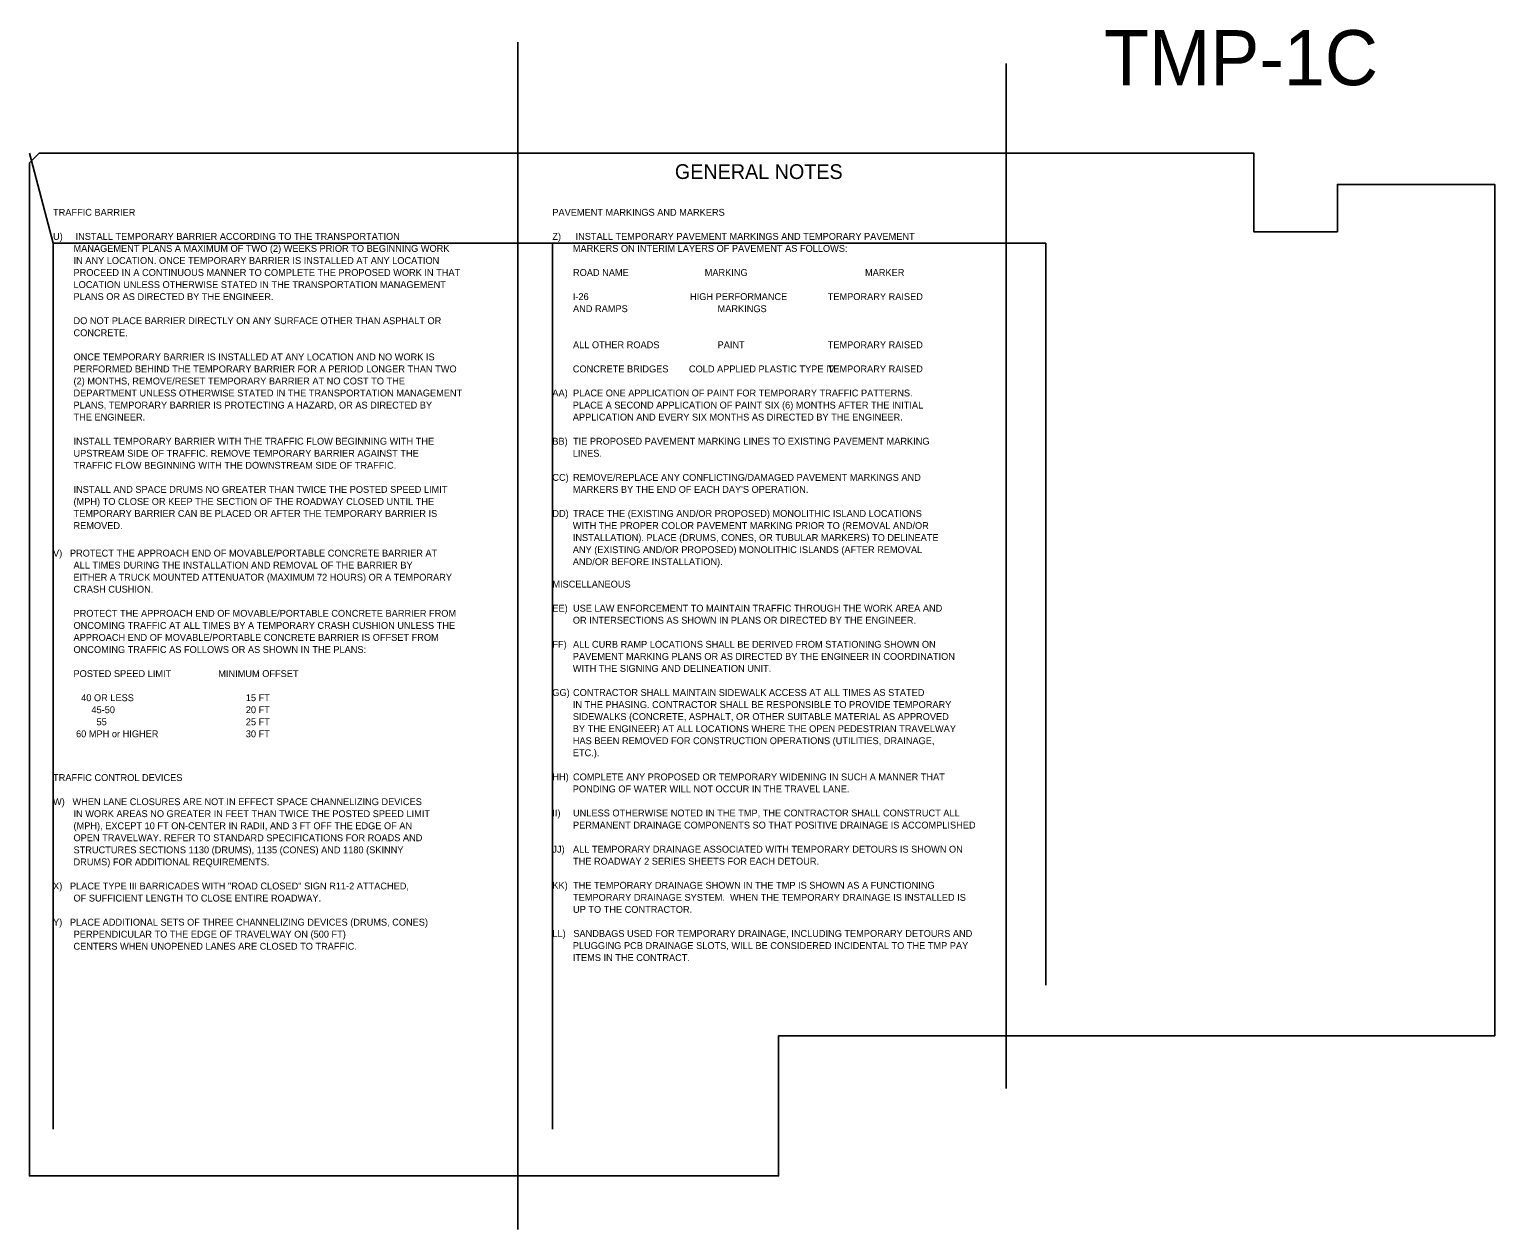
# Model space of a CAD drawing. Extents: x 2485109 to 2490507, y 368607 to 371384.
# Drawn here: x 2489017 to 2490507, y 370164 to 371384 of the extents above; entities that cross this region are included whole.
import ezdxf

# ---------------------------------------------------------------- set-up
doc = ezdxf.new("R2010")
doc.units = 0
for name, color, linetype in [('Scratch_Level_2', 7, 'Continuous'), ('Scratch_Level_3', 7, 'Continuous'), ('Scratch_Level_4', 7, 'Continuous'), ('TC SHEET LAYOUT SHAPE', 7, 'Continuous'), ('TC SHEET TEXT', 7, 'Continuous')]:
    doc.layers.add(name, color=color, linetype=linetype)

msp = doc.modelspace()

# ---------------------------------------------------------------- linework, layer by layer
at = {"layer": 'Scratch_Level_2'}
for p, q in [((2489513.2, 370163.7), (2489513.2, 371371.1)), ((2490009.9, 370307.3), (2490009.9, 371349.4))]:
    msp.add_line(p, q, dxfattribs=at)
at = {"layer": 'Scratch_Level_3'}
msp.add_line((2489016.6, 371258.3), (2489016.6, 371258.3), dxfattribs=at)
at = {"layer": 'Scratch_Level_4'}
for p, q in [((2489016.6, 371258.3), (2489040.7, 371166.6)), ((2489040.7, 371166.6), (2489040.7, 370266)), ((2489040.7, 371166.6), (2490050.1, 371166.6)), ((2489548.4, 371166.6), (2489548.4, 370266)), ((2490050.1, 371166.6), (2490050.1, 370412.4))]:
    msp.add_line(p, q, dxfattribs=at)
at = {"layer": 'TC SHEET LAYOUT SHAPE'}
msp.add_lwpolyline([(2489016.6, 370666.8), (2489016.6, 370976.2), (2489016.6, 371248.3), (2489026.6, 371258.3), (2489469.6, 371258.3), (2489940.6, 371258.3), (2490261.6, 371258.3), (2490261.6, 371178.3), (2490346.6, 371178.3), (2490346.6, 371226.3), (2490506.6, 371226.3), (2490506.6, 370891.3), (2490506.6, 370612.1), (2490506.6, 370360.8), (2489778.4, 370360.8), (2489778.4, 370218.3), (2489608.9, 370218.3), (2489256.1, 370218.3), (2489016.6, 370218.3)], close=True, dxfattribs=at)

# ---------------------------------------------------------------- texts
msp.add_text('TMP-1C', height=56, rotation=0.0001, dxfattribs=at).set_placement((2490109.2, 371327.2))
at = {"layer": 'TC SHEET TEXT'}
msp.add_text('GENERAL NOTES', height=15, rotation=359.994, dxfattribs=at).set_placement((2489673, 371231.9))
for s, p in [('TRAFFIC BARRIER', (2489040.7, 371194.5)), ('PAVEMENT MARKINGS AND MARKERS', (2489548.4, 371194.5)), ('U)     INSTALL TEMPORARY BARRIER ACCORDING TO THE TRANSPORTATION', (2489040.7, 371170)), ('Z)', (2489548.4, 371170)), (' INSTALL TEMPORARY PAVEMENT MARKINGS AND TEMPORARY PAVEMENT', (2489569.4, 371170)), ('        MANAGEMENT PLANS A MAXIMUM OF TWO (2) WEEKS PRIOR TO BEGINNING WORK', (2489040.7, 371157.8)), ('        MARKERS ON INTERIM LAYERS OF PAVEMENT AS FOLLOWS:', (2489548.4, 371157.8)), ('        IN ANY LOCATION. ONCE TEMPORARY BARRIER IS INSTALLED AT ANY LOCATION', (2489040.7, 371145.5)), ('        PROCEED IN A CONTINUOUS MANNER TO COMPLETE THE PROPOSED WORK IN THAT', (2489040.7, 371133.3)), ('ROAD NAME', (2489569.4, 371133.3)), ('MARKING', (2489703.3, 371133.3)), ('MARKER', (2489866.3, 371133.3)), ('        LOCATION UNLESS OTHERWISE STATED IN THE TRANSPORTATION MANAGEMENT', (2489040.7, 371121)), ('        PLANS OR AS DIRECTED BY THE ENGINEER.', (2489040.7, 371108.8)), ('        I-26', (2489548.4, 371108.8)), ('HIGH PERFORMANCE', (2489688.4, 371108.8)), ('TEMPORARY RAISED', (2489828.4, 371108.8)), ('AND RAMPS', (2489569.4, 371096.5)), ('MARKINGS', (2489716.4, 371096.5)), ('        DO NOT PLACE BARRIER DIRECTLY ON ANY SURFACE OTHER THAN ASPHALT OR', (2489040.7, 371084.3)), ('        CONCRETE.', (2489040.7, 371072)), ('ALL OTHER ROADS                   ', (2489569.4, 371059.8)), ('PAINT             ', (2489716.4, 371059.8)), ('TEMPORARY RAISED', (2489828.4, 371059.8)), ('        ONCE TEMPORARY BARRIER IS INSTALLED AT ANY LOCATION AND NO WORK IS', (2489040.7, 371047.5)), ('        PERFORMED BEHIND THE TEMPORARY BARRIER FOR A PERIOD LONGER THAN TWO', (2489040.7, 371035.3)), ('        CONCRETE BRIDGES        COLD APPLIED PLASTIC TYPE IV', (2489548.4, 371035.3)), ('TEMPORARY RAISED', (2489828.4, 371035.3)), ('        (2) MONTHS, REMOVE/RESET TEMPORARY BARRIER AT NO COST TO THE', (2489040.7, 371023)), ('        DEPARTMENT UNLESS OTHERWISE STATED IN THE TRANSPORTATION MANAGEMENT', (2489040.7, 371010.8)), ('AA)', (2489548.4, 371010.8)), ('PLACE ONE APPLICATION OF PAINT FOR TEMPORARY TRAFFIC PATTERNS.', (2489569.4, 371010.8)), ('        PLANS, TEMPORARY BARRIER IS PROTECTING A HAZARD, OR AS DIRECTED BY', (2489040.7, 370998.5)), ('        PLACE A SECOND APPLICATION OF PAINT SIX (6) MONTHS AFTER THE INITIAL', (2489548.4, 370998.5)), ('        THE ENGINEER.', (2489040.7, 370986.3)), ('        APPLICATION AND EVERY SIX MONTHS AS DIRECTED BY THE ENGINEER.', (2489548.4, 370986.3)), ('        INSTALL TEMPORARY BARRIER WITH THE TRAFFIC FLOW BEGINNING WITH THE', (2489040.7, 370961.8)), ('BB)', (2489548.4, 370961.8)), ('TIE PROPOSED PAVEMENT MARKING LINES TO EXISTING PAVEMENT MARKING', (2489569.4, 370961.8)), ('        UPSTREAM SIDE OF TRAFFIC. REMOVE TEMPORARY BARRIER AGAINST THE', (2489040.7, 370949.5)), ('        LINES.', (2489548.4, 370949.5)), ('        TRAFFIC FLOW BEGINNING WITH THE DOWNSTREAM SIDE OF TRAFFIC. ', (2489040.7, 370937.3)), ('CC)', (2489548.4, 370925)), ('REMOVE/REPLACE ANY CONFLICTING/DAMAGED PAVEMENT MARKINGS AND', (2489569.4, 370925)), ('        (MPH) TO CLOSE OR KEEP THE SECTION OF THE ROADWAY CLOSED UNTIL THE', (2489040.7, 370900.5)), ('        INSTALL AND SPACE DRUMS NO GREATER THAN TWICE THE POSTED SPEED LIMIT', (2489040.7, 370912.8)), ("        MARKERS BY THE END OF EACH DAY'S OPERATION.", (2489548.4, 370912.8)), ('        TEMPORARY BARRIER CAN BE PLACED OR AFTER THE TEMPORARY BARRIER IS', (2489040.7, 370888.3)), ('DD)', (2489548.4, 370888.3)), ('TRACE THE (EXISTING AND/OR PROPOSED) MONOLITHIC ISLAND LOCATIONS', (2489569.4, 370888.3)), ('        REMOVED.', (2489040.7, 370876)), ('        WITH THE PROPER COLOR PAVEMENT MARKING PRIOR TO (REMOVAL AND/OR', (2489548.4, 370876)), ('        INSTALLATION). PLACE (DRUMS, CONES, OR TUBULAR MARKERS) TO DELINEATE', (2489548.4, 370863.8)), ('V)   PROTECT THE APPROACH END OF MOVABLE/PORTABLE CONCRETE BARRIER AT', (2489040.7, 370848)), ('        ANY (EXISTING AND/OR PROPOSED) MONOLITHIC ISLANDS (AFTER REMOVAL', (2489548.4, 370851.5)), ('        ALL TIMES DURING THE INSTALLATION AND REMOVAL OF THE BARRIER BY', (2489040.7, 370835.8)), ('        AND/OR BEFORE INSTALLATION).', (2489548.4, 370839.3)), ('        CRASH CUSHION. ', (2489040.7, 370811.3)), ('        EITHER A TRUCK MOUNTED ATTENUATOR (MAXIMUM 72 HOURS) OR A TEMPORARY', (2489040.7, 370823.5)), ('MISCELLANEOUS', (2489548.4, 370816.5)), ('        PROTECT THE APPROACH END OF MOVABLE/PORTABLE CONCRETE BARRIER FROM', (2489040.7, 370786.8)), ('EE)', (2489548.4, 370792)), ('USE LAW ENFORCEMENT TO MAINTAIN TRAFFIC THROUGH THE WORK AREA AND', (2489569.4, 370792)), ('        ONCOMING TRAFFIC AT ALL TIMES BY A TEMPORARY CRASH CUSHION UNLESS THE', (2489040.7, 370774.5)), ('        OR INTERSECTIONS AS SHOWN IN PLANS OR DIRECTED BY THE ENGINEER.', (2489548.4, 370779.8)), ('        APPROACH END OF MOVABLE/PORTABLE CONCRETE BARRIER IS OFFSET FROM', (2489040.7, 370762.3)), ('FF)', (2489548.4, 370755.3)), ('ALL CURB RAMP LOCATIONS SHALL BE DERIVED FROM STATIONING SHOWN ON', (2489569.4, 370755.3)), ('        ONCOMING TRAFFIC AS FOLLOWS OR AS SHOWN IN THE PLANS: ', (2489040.7, 370750)), ('        PAVEMENT MARKING PLANS OR AS DIRECTED BY THE ENGINEER IN COORDINATION', (2489548.4, 370743)), ('        POSTED SPEED LIMIT ', (2489040.7, 370725.5)), ('MINIMUM OFFSET', (2489208.7, 370725.5)), ('        WITH THE SIGNING AND DELINEATION UNIT.', (2489548.4, 370730.8)), ('GG)', (2489548.4, 370706.3)), ('CONTRACTOR SHALL MAINTAIN SIDEWALK ACCESS AT ALL TIMES AS STATED', (2489569.4, 370706.3)), ('           40 OR LESS      ', (2489040.7, 370701)), ('15 FT', (2489236.7, 370701)), ('        IN THE PHASING. CONTRACTOR SHALL BE RESPONSIBLE TO PROVIDE TEMPORARY', (2489548.4, 370694)), ('               45-50     ', (2489040.7, 370688.8)), ('                 55      ', (2489040.7, 370676.5)), ('20 FT', (2489236.7, 370688.8)), ('25 FT', (2489236.7, 370676.5)), ('        SIDEWALKS (CONCRETE, ASPHALT, OR OTHER SUITABLE MATERIAL AS APPROVED', (2489548.4, 370681.8)), ('         60 MPH or HIGHER      ', (2489040.7, 370664.3)), ('30 FT', (2489236.7, 370664.3)), ('        BY THE ENGINEER) AT ALL LOCATIONS WHERE THE OPEN PEDESTRIAN TRAVELWAY', (2489548.4, 370669.5)), ('        HAS BEEN REMOVED FOR CONSTRUCTION OPERATIONS (UTILITIES, DRAINAGE,', (2489548.4, 370657.3)), ('        ETC.).', (2489548.4, 370645)), ('TRAFFIC CONTROL DEVICES', (2489040.7, 370619.8)), ('HH)', (2489548.4, 370620.5)), ('COMPLETE ANY PROPOSED OR TEMPORARY WIDENING IN SUCH A MANNER THAT', (2489569.4, 370620.5)), ('        PONDING OF WATER WILL NOT OCCUR IN THE TRAVEL LANE.', (2489548.4, 370608.3)), ('W)   WHEN LANE CLOSURES ARE NOT IN EFFECT SPACE CHANNELIZING DEVICES', (2489040.7, 370595.3)), ('        IN WORK AREAS NO GREATER IN FEET THAN TWICE THE POSTED SPEED LIMIT', (2489040.7, 370583.1)), ('II)', (2489548.4, 370583.8)), ('UNLESS OTHERWISE NOTED IN THE TMP, THE CONTRACTOR SHALL CONSTRUCT ALL', (2489569.4, 370583.8)), ('        OPEN TRAVELWAY. REFER TO STANDARD SPECIFICATIONS FOR ROADS AND', (2489040.7, 370558.6)), ('        (MPH), EXCEPT 10 FT ON-CENTER IN RADII, AND 3 FT OFF THE EDGE OF AN', (2489040.7, 370570.8)), ('PERMANENT DRAINAGE COMPONENTS SO THAT POSITIVE DRAINAGE IS ACCOMPLISHED', (2489569.4, 370571.5)), ('        STRUCTURES SECTIONS 1130 (DRUMS), 1135 (CONES) AND 1180 (SKINNY', (2489040.7, 370546.3)), ('JJ)', (2489548.4, 370547)), ('ALL TEMPORARY DRAINAGE ASSOCIATED WITH TEMPORARY DETOURS IS SHOWN ON', (2489569.4, 370547)), ('        DRUMS) FOR ADDITIONAL REQUIREMENTS.', (2489040.7, 370534.1)), ('THE ROADWAY 2 SERIES SHEETS FOR EACH DETOUR.', (2489569.4, 370534.8)), ('X)   PLACE TYPE III BARRICADES WITH "ROAD CLOSED" SIGN R11-2 ATTACHED,', (2489040.7, 370509.6)), ('        OF SUFFICIENT LENGTH TO CLOSE ENTIRE ROADWAY.', (2489040.7, 370497.3)), ('KK)', (2489548.4, 370510.3)), ('THE TEMPORARY DRAINAGE SHOWN IN THE TMP IS SHOWN AS A FUNCTIONING', (2489569.4, 370510.3)), ('TEMPORARY DRAINAGE SYSTEM.  WHEN THE TEMPORARY DRAINAGE IS INSTALLED IS', (2489569.4, 370498)), ('UP TO THE CONTRACTOR.', (2489569.4, 370485.8)), ('Y)   PLACE ADDITIONAL SETS OF THREE CHANNELIZING DEVICES (DRUMS, CONES)', (2489040.7, 370472.8)), ('PERPENDICULAR TO THE EDGE OF TRAVELWAY ON (500 FT)', (2489061.7, 370460.6)), ('LL)   SANDBAGS USED FOR TEMPORARY DRAINAGE, INCLUDING TEMPORARY DETOURS AND ', (2489548.4, 370461.3)), ('        CENTERS WHEN UNOPENED LANES ARE CLOSED TO TRAFFIC.', (2489040.7, 370448.3)), ('        PLUGGING PCB DRAINAGE SLOTS, WILL BE CONSIDERED INCIDENTAL TO THE TMP PAY', (2489548.4, 370449)), ('        ITEMS IN THE CONTRACT.', (2489548.4, 370436.8))]:
    msp.add_text(s, height=7, dxfattribs=at).set_placement(p)

doc.saveas('drawing.dxf')
